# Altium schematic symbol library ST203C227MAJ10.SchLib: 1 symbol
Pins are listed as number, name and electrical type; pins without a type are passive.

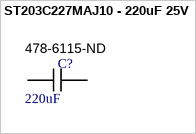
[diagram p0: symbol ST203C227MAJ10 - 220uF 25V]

## ST203C227MAJ10 - 220uF 25V
designator C?, comment Supplier Part Number: 478-6115-ND  (hidden comment: 220uF)
CAP CER 220UF 25V 20% X7R SMD; Part Number: ST203C227MAJ10; Manufacturer: AVX Corporation; Voltage: 25; Value: 220µF
footprint AVX-ST20-J10
pins: 1, 2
